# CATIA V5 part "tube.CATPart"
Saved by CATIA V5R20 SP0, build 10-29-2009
Part number: Tube
Bounding box of the stored display mesh (mm): x -22.5 to 22.5, y -22.404 to 76, z -27 to 27
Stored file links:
  D:\OneDrive\OneDrive - 한양대학교\문서\Teaching\2021\CAD\Final Exam\oscillation motion\tube.CATPart
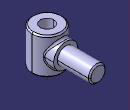
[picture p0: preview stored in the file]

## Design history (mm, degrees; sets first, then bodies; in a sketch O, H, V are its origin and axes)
Body1 (main body)
  Sketch1 on xy-plane, origin (0, 0, 0), H (1, 0, 0), V (0, 1, 0)
    circle A1 centre (0, 0) radius 10
    circle A2 centre (0, 0) radius 22.5
    point P2 (0, 0)
    radius A2 = 22.5
    radius A1 = 10
    coincidence: P2 O
    concentricity: A1 A2
  Pad1: profile Sketch1, direction (0, 0, 1), length 27, mirrored extent
  Plane1: type Offset, RefPlane zx-plane, Offset 13
  Sketch2 on Plane1, origin (0, 13, 0), H (-1, 0, 0), V (0, 0, 1)
    circle A1 centre (0, 0) radius 18
    radius A1 = 18
  Pad2: profile Sketch2, direction (0, 1, 0), length 15
  Sketch3 on end face of Pad2, origin (0, 28, 0), H (-1, 0, 0), V (0, 0, 1)
    circle A1 centre (0, 0) radius 12.5
    radius A1 = 12.5
  Pad3: profile Sketch3, direction (0, 1, 0), length 48
  Chamfer1: length 2, angle 45, on edge [face of Pad3 from Sketch3.A1 | end face of Pad3]; edge [face of Pad1 from Sketch1.A2 | end face of Pad1]
  Chamfer2: length 2, angle 45, on edge [start face of Pad1 | face of Pad1 from Sketch1.A2]
  Fillet1: radius 3, on edge [face of Pad1 from Sketch1.A2 | face of Pad2 from Sketch2.A1]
